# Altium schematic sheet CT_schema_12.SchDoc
size 281 x 153 mm
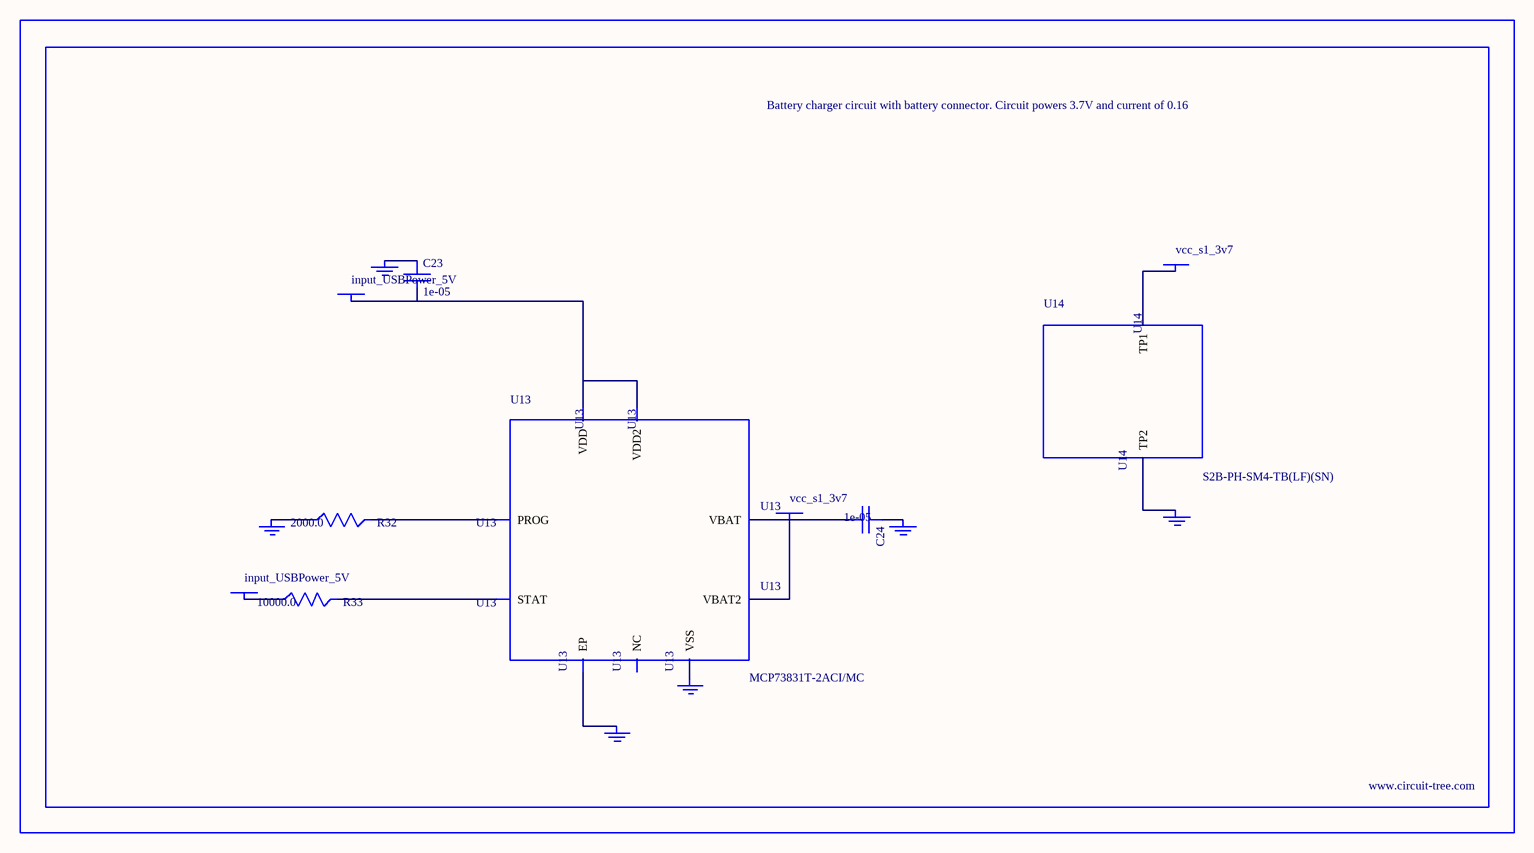
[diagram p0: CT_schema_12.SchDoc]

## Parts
BORDER11  (no value)
C23  1e-05  [C1206]
C24  1e-05  [C1206]
GND_INSTANCE_11_0  (no value)
GND_INSTANCE_11_1  (no value)
GND_INSTANCE_11_2  (no value)
GND_INSTANCE_11_3  (no value)
GND_INSTANCE_11_4  (no value)
GND_INSTANCE_11_5  (no value)
POWER_INSTANCE_11_0  input_USBPower_5V
POWER_INSTANCE_11_1  input_USBPower_5V
POWER_INSTANCE_11_2  vcc_s1_3v7
POWER_INSTANCE_11_3  vcc_s1_3v7
R32  2000.0  [R0603]
R33  10000.0  [R0603]
U13  MCP73831T-2ACI/MC  [DFN8_2X3MC]
U14  S2B-PH-SM4-TB(LF)(SN)  [JST-2-SMD]

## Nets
NetC23_1: C23.1 GND_INSTANCE_11_0.0(GND)
NetC23_2: C23.2 POWER_INSTANCE_11_0.0(PWR) U13.1(VDD) U13.2(VDD2)
NetC24_1: C24.1 GND_INSTANCE_11_1.0(GND)
NetC24_2: C24.2 POWER_INSTANCE_11_2.0(PWR) U13.3(VBAT) U13.4(VBAT2)
NetGND_INSTANCE_11_2_0: GND_INSTANCE_11_2.0(GND) R32.1
NetGND_INSTANCE_11_3_0: GND_INSTANCE_11_3.0(GND) U13.9(EP)
NetGND_INSTANCE_11_4_0: GND_INSTANCE_11_4.0(GND) U13.6(VSS)
NetGND_INSTANCE_11_5_0: GND_INSTANCE_11_5.0(GND) U14.2(TP2)
NetPOWER_INSTANCE_11_1_0: POWER_INSTANCE_11_1.0(PWR) R33.1
NetPOWER_INSTANCE_11_3_0: POWER_INSTANCE_11_3.0(PWR) U14.1(TP1)
NetR32_2: R32.2 U13.8(PROG)
NetR33_2: R33.2 U13.5(STAT)

Not connected (* = marked no-connect by the designer): U13 7(NC)

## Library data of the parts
BORDER11 = BORDER_PAGE11
C23 C24 = C1206C106K3RACTU
GND_INSTANCE_11_0-GND_INSTANCE_11_5 = GND
POWER_INSTANCE_11_0-POWER_INSTANCE_11_3 = PWR
R32 = RC0603JR-072KL
R33 = RC0603JR-0710KL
